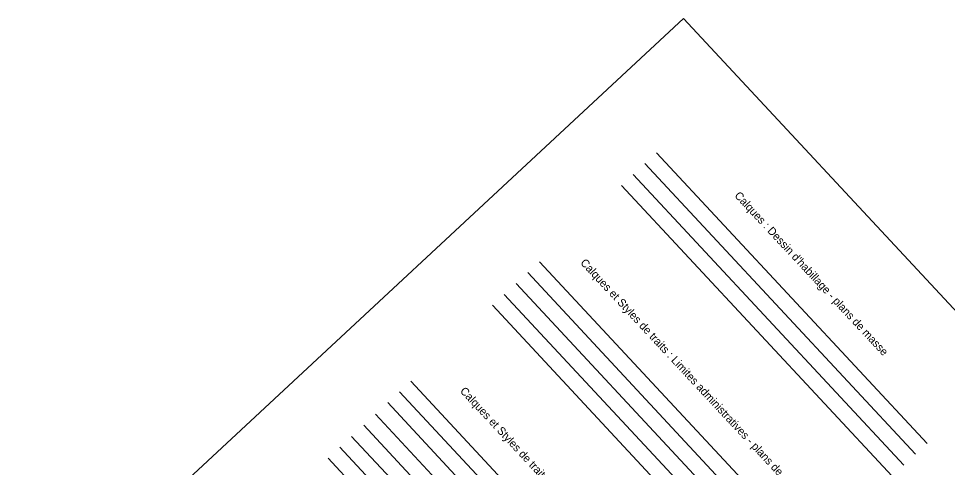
# Model space of a CAD drawing. Extents: x 704383 to 706615, y 7057567 to 7059313.
# Drawn here: x 706440.3 to 706498.3, y 7057783.5 to 7057811.5 of the extents above; entities that cross this region are included whole.
import ezdxf

# ---------------------------------------------------------------- set-up
doc = ezdxf.new("R2010")
doc.units = 0
for name, color, linetype in [('DH_CADRE -CARTOUCHE', 7, 'Continuous'), ('LIM_ADM ARRONDISSEMENT', 7, 'Continuous'), ('LIM_ADM DEPARTEMENT', 7, 'Continuous'), ('LIM_ADM_CADASTRE', 7, 'Continuous'), ('LIM_ADM_CHAMP TIR', 7, 'Continuous'), ('LIM_ADM_COMMUNE', 7, 'Continuous'), ('MASSE_DH_COTATION', 7, 'Continuous'), ('MASSE_DH_HACHURE-MOTIF', 7, 'Continuous'), ('MASSE_DH_PERSONNAGE_VEHICULES', 7, 'Continuous'), ('MASSE_DH_TEXTE', 7, 'Continuous'), ('R_MED_OXYGENE_CANALISATION_CL_A', 7, 'Continuous'), ('R_MED_OXYGENE_CANALISATION_CL_B', 7, 'Continuous'), ('R_MED_OXYGENE_CANALISATION_CL_C', 7, 'Continuous'), ('R_MED_OXYGENE_EQUIP', 7, 'Continuous'), ('R_MED_OXYGENE_TEXTE', 7, 'Continuous'), ('R_MED_VIDE_CANALISATION_CL_A', 7, 'Continuous'), ('R_MED_VIDE_CANALISATION_CL_B', 7, 'Continuous'), ('R_MED_VIDE_CANALISATION_CL_C', 7, 'Continuous')]:
    doc.layers.add(name, color=color, linetype=linetype)

msp = doc.modelspace()

# ---------------------------------------------------------------- linework, layer by layer
at = {"layer": 'DH_CADRE -CARTOUCHE'}
msp.add_lwpolyline([(706481.837, 7057811.547), (706566.98, 7057720.028), (706402.247, 7057566.771), (706317.104, 7057658.289)], close=True, dxfattribs=at)
at = {"layer": 'LIM_ADM ARRONDISSEMENT'}
msp.add_line((706472.838, 7057796.346), (706489.744, 7057778.174), dxfattribs=at)
at = {"layer": 'LIM_ADM DEPARTEMENT'}
msp.add_line((706472.106, 7057795.664), (706489.012, 7057777.492), dxfattribs=at)
at = {"layer": 'LIM_ADM_CADASTRE'}
msp.add_line((706488.28, 7057776.811), (706471.374, 7057794.983), dxfattribs=at)
at = {"layer": 'LIM_ADM_CHAMP TIR'}
msp.add_line((706470.641, 7057794.302), (706487.548, 7057776.13), dxfattribs=at)
at = {"layer": 'LIM_ADM_COMMUNE'}
msp.add_line((706469.909, 7057793.621), (706486.815, 7057775.449), dxfattribs=at)
at = {"layer": 'MASSE_DH_COTATION'}
msp.add_line((706480.159, 7057803.157), (706497.066, 7057784.985), dxfattribs=at)
at = {"layer": 'MASSE_DH_HACHURE-MOTIF'}
msp.add_line((706496.333, 7057784.304), (706479.427, 7057802.476), dxfattribs=at)
at = {"layer": 'MASSE_DH_PERSONNAGE_VEHICULES'}
msp.add_line((706495.601, 7057783.623), (706478.695, 7057801.795), dxfattribs=at)
at = {"layer": 'MASSE_DH_TEXTE'}
msp.add_line((706494.869, 7057782.942), (706477.963, 7057801.114), dxfattribs=at)
at = {"layer": 'R_MED_OXYGENE_CANALISATION_CL_A'}
msp.add_line((706464.807, 7057788.874), (706481.709, 7057770.706), dxfattribs=at)
at = {"layer": 'R_MED_OXYGENE_CANALISATION_CL_B'}
msp.add_line((706464.098, 7057788.214), (706481, 7057770.046), dxfattribs=at)
at = {"layer": 'R_MED_OXYGENE_CANALISATION_CL_C'}
msp.add_line((706463.365, 7057787.533), (706480.268, 7057769.365), dxfattribs=at)
at = {"layer": 'R_MED_OXYGENE_EQUIP'}
msp.add_line((706479.49, 7057768.641), (706462.588, 7057786.81), dxfattribs=at)
at = {"layer": 'R_MED_OXYGENE_TEXTE'}
msp.add_line((706478.758, 7057767.96), (706461.856, 7057786.128), dxfattribs=at)
at = {"layer": 'R_MED_VIDE_CANALISATION_CL_A'}
msp.add_line((706461.101, 7057785.426), (706477.993, 7057767.269), dxfattribs=at)
at = {"layer": 'R_MED_VIDE_CANALISATION_CL_B'}
msp.add_line((706460.369, 7057784.745), (706477.261, 7057766.588), dxfattribs=at)
at = {"layer": 'R_MED_VIDE_CANALISATION_CL_C'}
msp.add_line((706459.637, 7057784.064), (706476.529, 7057765.907), dxfattribs=at)

# ---------------------------------------------------------------- texts
at = {"layer": 'DH_CADRE -CARTOUCHE'}
for s, p in [("Calques : Dessin d'habillage - plans de masse", (706484.991, 7057800.449)), ('Calques et Styles de traits : Limites administratives - plans de masse', (706475.36, 7057796.249)), (' Calques et Styles de traits: Réseaux médicaux - plans de masse', (706467.712, 7057788.366))]:
    msp.add_text(s, height=0.5, rotation=312.93319, dxfattribs=at).set_placement(p)

doc.saveas('drawing.dxf')
